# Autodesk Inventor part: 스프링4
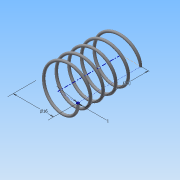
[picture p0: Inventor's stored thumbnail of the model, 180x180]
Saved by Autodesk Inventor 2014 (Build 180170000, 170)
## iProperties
Created: 2015-06
Part Number: 스프링4
Material: 강철, 연강
Document SubType Name: Modeling
Designer: Administrator
Density: 7.86 g/cm^3
Appearance: 강철
Mass: 1.52988 g
Surface Area: 7.87024 cm^2
Volume: 0.194641 cm^3
Author: Administrator
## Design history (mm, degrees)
sketch "스케치1"
  geometry: L1 (0, 0)-(8, 0); L2 (8, 0)-(8, 14.5); L3 (8, 14.5)-(0, 14.5); L4 (0, 14.5)-(0, 0); C1 r 0.5 at (8, 0)
  constraints: 8 end point, 2 parallel, 1 centre point, 1 coincident, 1 horizontal, 1 perpendicular
  dimensions: "d0" = 16 diameter of L2 L4; "d1" = 14.5 distance of L1.end L2.end (derived); "d2" = 1 diameter of C1
feature "코일1" sketch "스케치1" pitch "d3" = 10; turns "d5" = 5; dims "d4" = 14.5 (= d1), "d6" = 0, angle "d7" = 90 deg, angle "d8" = 90 deg, "d9" = 0, "d10" = 0
node "작업 평면1"
sketch "스케치2"
  geometry: L1 (-8.5, 0)-(-7.5, 0) reference; 1 further point
  constraints: 1 horizontal alignment
extrude "돌출1" cut sketch "스케치2" stored distance "d12" = 10; taper "d13" = 0 deg
node "작업 평면2"
sketch "스케치3"
  geometry: L1 (-7.5, 0)-(-8.5, 0) reference; 1 further point
  constraints: 1 horizontal alignment
extrude "돌출2" cut sketch "스케치3" stored distance "d15" = 10; taper "d16" = 0 deg
node "솔리드1"
node "절단 모서리 투영1"
node "절단 모서리 투영2"
other parameters: "d11" = 0, "d14" = 14.5 (= d1)
